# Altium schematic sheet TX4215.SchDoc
size A0
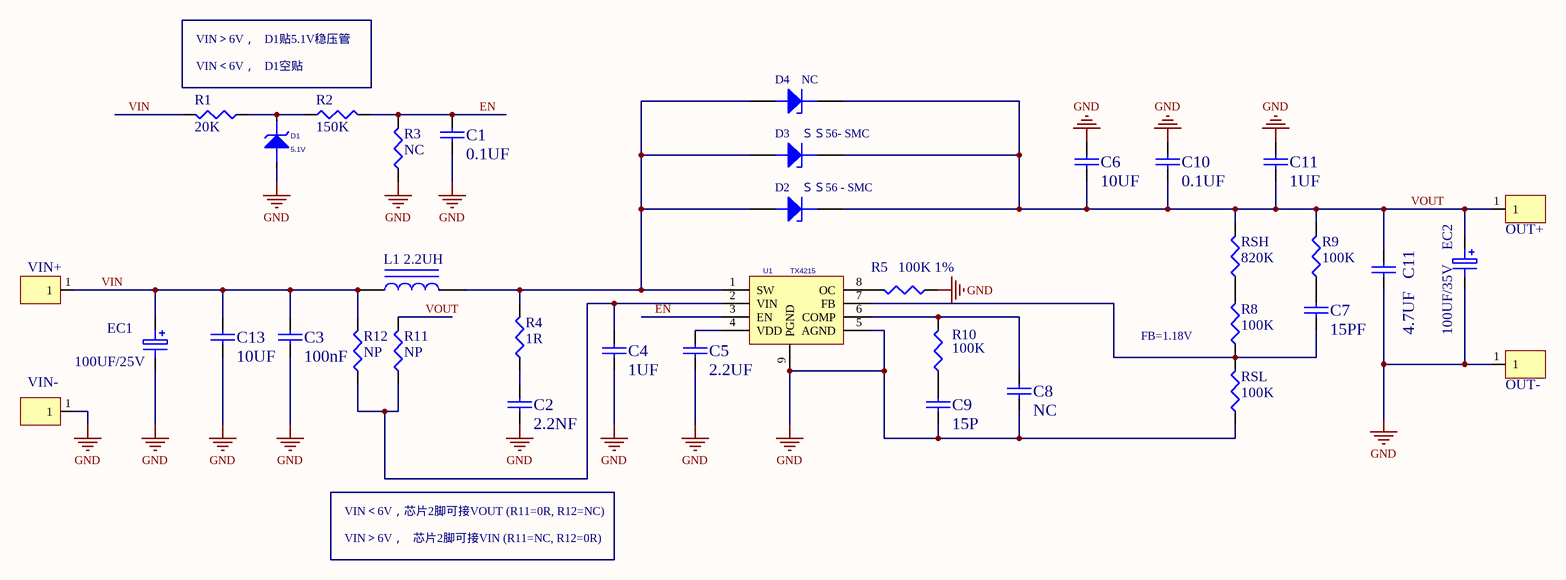
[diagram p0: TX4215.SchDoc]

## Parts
(Parts that share a designator on the sheet are numbered #1, #2 ... from top to bottom, then left to right.)
?  VIN-  [pad]
A#1  OUT+  [pad]
A#2  VIN+  [pad]
A#3  OUT-  [pad]
C1  0.1UF
C2  2.2NF
C3  100nF
C4  1UF
C5  2.2UF
C6  10UF
C7  15PF
C8  NC
C9  15P
C10  0.1UF
C11#1  1UF
C11#2  4.7UF
C13  10UF
D1  5.1V  [SOD-123]
D2_ＳＳ56_-_SMC  (no value)
D3_ＳＳ56-_SMC  (no value)
D4_NC  (no value)
EC1  100UF/25V  [C6.3*2.5]
EC2  100UF/35V  [C6.3*2.5]
L1_2.2UH  (no value)  [ls12*12]
R1  20K  [r1206]
R2  150K  [r1206]
R3  NC  [r1206]
R4  1R  [r1206]
R5  100K 1%  [r1206]
R8  100K  [r1206]
R9  100K  [r1206]
R10  100K  [r1206]
R11  NP  [r1206]
R12  NP  [r1206]
RSH  820K  [r1206]
RSL  100K  [r1206]
U1  TX4215  [ESOP-8(150MIL)]

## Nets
GND: ?.1 A#3.1 C1.1 C2.1 C3.2 C4.1 C5.1 C6.1 C8.1 C9.1 C10.2 C11#1.2 C11#2.2 C13.2 D1.2 EC1.2 EC2.2 R3.1 R5.1 RSL.1 U1.5(AGND) U1.9(PGND)
EN: C1.2 R2.2 R3.2 U1.3(EN)
VIN: A#2.1 C3.1 C13.1 EC1.1 L1_2.2UH.2 R1.2 R12.2
VOUT: A#1.1 C6.2 C10.1 C11#1.1 C11#2.1 D2_ＳＳ56_-_SMC.2(K) D3_ＳＳ56-_SMC.2(K) D4_NC.2(K) EC2.1 R9.2 R11.2 RSH.2
NetC2_2: C2.2 R4.1
NetC4_2: C4.2 R11.1 R12.1 U1.2(VIN)
NetC5_2: C5.2 U1.4(VDD)
NetC7_1: C7.1 R8.1 RSL.2 U1.7(FB)
NetC7_2: C7.2 R9.1
NetC8_2: C8.2 R10.2 U1.6(COMP)
NetC9_2: C9.2 R10.1
NetD1_1: D1.1 R1.1 R2.1
NetD2_ＳＳ56_-_SMC_1: D2_ＳＳ56_-_SMC.1(A) D3_ＳＳ56-_SMC.1(A) D4_NC.1(A) L1_2.2UH.1 R4.2 U1.1(SW)
NetR5_2: R5.2 U1.8(OC)
NetR8_2: R8.2 RSH.1

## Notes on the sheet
- VIN＞6V，   D1贴5.1V稳压管
- VIN＜6V，   D1空贴
- FB=1.18V
- VIN＜6V，芯片2脚可接VOUT (R11=0R, R12=NC)
- VIN＞6V，   芯片2脚可接VIN (R11=NC, R12=0R)

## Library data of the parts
? A#1-A#3 = IN
C1-C10 C11#1 C11#2 C13 = CAP: Capacitor
D1 = 二极管_稳压
D2_ＳＳ56_-_SMC D3_ＳＳ56-_SMC D4_NC = ZENER1: Zener Diode
EC1 EC2 = C
L1_2.2UH = INDUCTOR IRON
R1-R5 R8-R12 RSH RSL = RES1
